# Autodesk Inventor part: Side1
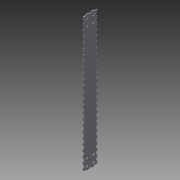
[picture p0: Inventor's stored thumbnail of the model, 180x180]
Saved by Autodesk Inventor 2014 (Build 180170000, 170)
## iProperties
Created: 2014-06
Part Number: Side1
Material: Generic
Document SubType Name: Modeling
Designer: Aser
Density: 1 g/cm^3
Appearance: Default
Author: Aser
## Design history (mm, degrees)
sketch "Sketch1"
  geometry: L1 (-22, 242)-(22, 242); L2 (22, 242)-(22, -242); L3 (22, -242)-(-22, -242); L4 (-22, -242)-(-22, 242); L5 (-22, 242)-(22, -242); L6 (22, 242)-(-22, -242); L7 (22, 242)-(25, 242); L8 (25, 242)-(25, 232); L9 (25, 232)-(22, 232); L10 (22, 232)-(22, 242); L11 (22, 222.25)-(25, 222.25); L12 (25, 222.25)-(25, 212.25); L13 (25, 212.25)-(22, 212.25); L14 (22, 212.25)-(22, 222.25); L15 (22, 202.5)-(25, 202.5); L16 (25, 202.5)-(25, 192.5); L17 (25, 192.5)-(22, 192.5); L18 (22, 192.5)-(22, 202.5); L19 (22, 182.75)-(25, 182.75); L20 (25, 182.75)-(25, 172.75); L21 (25, 172.75)-(22, 172.75); L22 (22, 172.75)-(22, 182.75); L23 (22, 163)-(25, 163); L24 (25, 163)-(25, 153); L25 (25, 153)-(22, 153); L26 (22, 153)-(22, 163); L27 (22, 143.25)-(25, 143.25); L28 (25, 143.25)-(25, 133.25); L29 (25, 133.25)-(22, 133.25); L30 (22, 133.25)-(22, 143.25); L31 (22, 123.5)-(25, 123.5); L32 (25, 123.5)-(25, 113.5); L33 (25, 113.5)-(22, 113.5); L34 (22, 113.5)-(22, 123.5); L35 (22, 103.75)-(25, 103.75); L36 (25, 103.75)-(25, 93.75); L37 (25, 93.75)-(22, 93.75); L38 (22, 93.75)-(22, 103.75); L39 (22, 84)-(25, 84); L40 (25, 84)-(25, 74); L41 (25, 74)-(22, 74); L42 (22, 74)-(22, 84); L43 (22, 64.25)-(25, 64.25); L44 (25, 64.25)-(25, 54.25); L45 (25, 54.25)-(22, 54.25); L46 (22, 54.25)-(22, 64.25); L47 (22, 44.5)-(25, 44.5); L48 (25, 44.5)-(25, 34.5); L49 (25, 34.5)-(22, 34.5); L50 (22, 34.5)-(22, 44.5); L51 (22, 24.75)-(25, 24.75); L52 (25, 24.75)-(25, 14.75); L53 (25, 14.75)-(22, 14.75); L54 (22, 14.75)-(22, 24.75); L55 (22, 5)-(25, 5); L56 (25, 5)-(25, -5); L57 (25, -5)-(22, -5); L58 (22, -5)-(22, 5); L59 (22, -14.75)-(25, -14.75); L60 (25, -14.75)-(25, -24.75); L61 (25, -24.75)-(22, -24.75); L62 (22, -24.75)-(22, -14.75); L63 (22, -34.5)-(25, -34.5); L64 (25, -34.5)-(25, -44.5)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; 1 further point
  constraints: 464 end point, 111 symmetric about line, 10 parallel, 6 perpendicular, 5 horizontal, 4 midpoint, 2 point on line, 1 vertical, 192 other
  dimensions: "d0" = 44 distance of L2.end L3.end; "d1" = 484 distance of L1.end L2.end; "d2" = 3 distance of L8.end L9.end; "d3" = 10 distance of L7.end L8.end; "d6" = 19.75 distance of L1.end L11.start; "d11" = 10 distance of L213.end L214.end; "d12" = 3 distance of L212.end L213.end; "d13" = 10 distance of L217.end L218.end; "d14" = 3 distance of L216.end L217.end; "d15" = 8 distance between parallel lines of L2 L215; "d16" = 8 distance between parallel lines of L219 L213; "d17" = 8 distance between parallel lines of L4 L217 (derived)
extrude "Extrusion1" new body sketch "Sketch1" distance "d18" = 3; taper "d19" = 0 deg
sketch "Sketch2"
  geometry: L1 (5, 25)-(-5, 25) reference; L2 (-222.25, 22)-(-232, 22) reference; L3 (-242, 25)-(-242, 14) reference; L4 (-5, -25)-(5, -25) reference; L5 (-245, 25)-(-195, 25); L6 (-195, 25)-(-195, -25); L7 (-195, -25)-(-245, -25); L8 (-245, -25)-(-245, 25); L9 (-245, 25)-(-195, -25); L10 (-195, 25)-(-245, -25); L11 (-232.5, -12.5)-(-207.5, -12.5); L12 (-207.5, -12.5)-(-207.5, 12.5); L13 (-207.5, 12.5)-(-232.5, 12.5); L14 (-232.5, 12.5)-(-232.5, -12.5); L15 (-232.5, -12.5)-(-207.5, 12.5); L16 (-207.5, -12.5)-(-232.5, 12.5); L17 (-237.5, 11)-(-227.5, 11); L18 (-227.5, 11)-(-227.5, 14); L19 (-227.5, 14)-(-237.5, 14); L20 (-237.5, 14)-(-237.5, 11); L21 (-237.5, 11)-(-227.5, 14); L22 (-227.5, 11)-(-237.5, 14); L23 (-234, 7.5)-(-231, 7.5); L24 (-231, 7.5)-(-231, 17.5); L25 (-231, 17.5)-(-234, 17.5); L26 (-234, 17.5)-(-234, 7.5); L27 (-234, 7.5)-(-231, 17.5); L28 (-231, 7.5)-(-234, 17.5); L29 (-209, 7.5)-(-206, 7.5); L30 (-202.5, 11)-(-202.5, 14); L31 (-206, 7.5)-(-206, 17.5); L32 (-212.5, 14)-(-212.5, 11); L33 (-202.5, 14)-(-212.5, 14); L34 (-212.5, 11)-(-202.5, 14); L35 (-202.5, 11)-(-212.5, 14); L36 (-209, 17.5)-(-209, 7.5); L37 (-206, 7.5)-(-209, 17.5); L38 (-209, 7.5)-(-206, 17.5); L39 (-212.5, 11)-(-202.5, 11); L40 (-206, 17.5)-(-209, 17.5); L41 (-234, -17.5)-(-231, -17.5); L42 (-227.5, -14)-(-227.5, -11); L43 (-231, -17.5)-(-231, -7.5); L44 (-237.5, -11)-(-237.5, -14); L45 (-227.5, -11)-(-237.5, -11); L46 (-237.5, -14)-(-227.5, -11); L47 (-227.5, -14)-(-237.5, -11); L48 (-234, -7.5)-(-234, -17.5); L49 (-231, -17.5)-(-234, -7.5); L50 (-234, -17.5)-(-231, -7.5); L51 (-237.5, -14)-(-227.5, -14); L52 (-231, -7.5)-(-234, -7.5); L53 (-209, -17.5)-(-206, -17.5); L54 (-202.5, -14)-(-202.5, -11); L55 (-206, -17.5)-(-206, -7.5); L56 (-212.5, -11)-(-212.5, -14); L57 (-202.5, -11)-(-212.5, -11); L58 (-212.5, -14)-(-202.5, -11); L59 (-202.5, -14)-(-212.5, -11); L60 (-209, -7.5)-(-209, -17.5); L61 (-206, -17.5)-(-209, -7.5); L62 (-209, -17.5)-(-206, -7.5); L63 (-212.5, -14)-(-202.5, -14); L64 (-206, -7.5)-(-209, -7.5)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; 9 further points
  constraints: 232 end point, 42 symmetric about line, 39 midpoint, 8 parallel, 5 horizontal, 4 perpendicular, 1 vertical, 63 other
  dimensions: "d20" = 50 distance of L6.end L7.end; "d21" = 50 distance of L5.end L6.end; "d22" = 3 distance between parallel lines of L2 L5; "d23" = 3 distance between parallel lines of L3 L8; "d24" = 25 distance of L13.end L12.end; "d25" = 25 distance of L12.end L11.end; "d26" = 10 distance of L19.end L18.end; "d27" = 3 distance of L18.end L17.end; "d28" = 3 distance of L25.end L24.end; "d29" = 10 distance of L24.end L23.end; "d32" = 25 distance of L23.start L29.start; "d35" = 25 distance of L23.start L41.start
extrude "Extrusion2" cut sketch "Sketch2" distance "d38" = 3; taper "d39" = 0 deg
body "Solid1"
